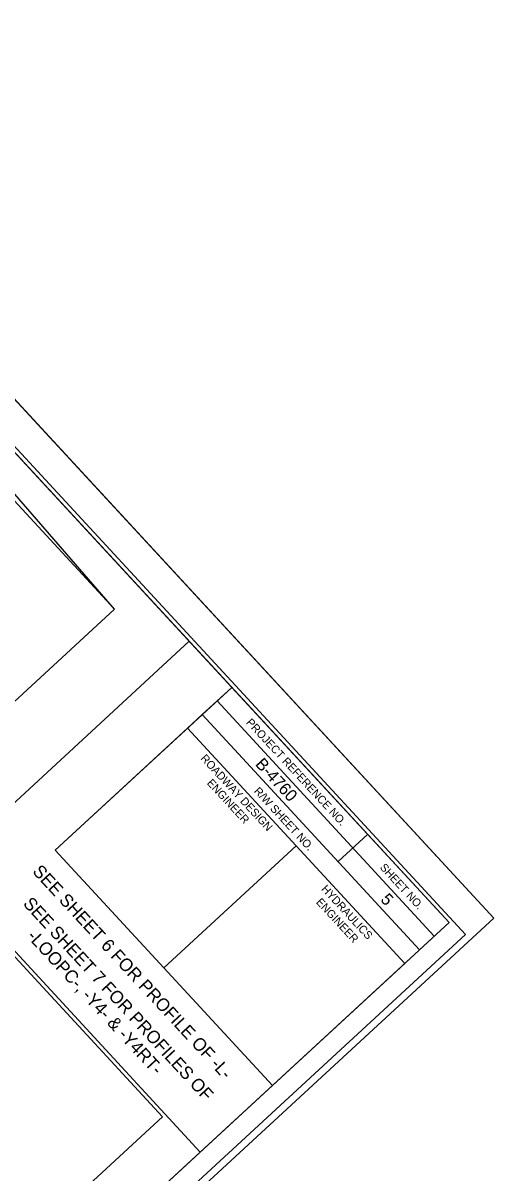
# Model space of a CAD drawing. Extents: x 1702837 to 1704783, y 793612 to 795591.
# Drawn here: x 1704489 to 1704783, y 794195 to 794914 of the extents above; entities that cross this region are included whole.
import ezdxf

# ---------------------------------------------------------------- set-up
doc = ezdxf.new("R2010")
doc.units = 0
for name, color, linetype in [('Old_Level_1', 7, 'Continuous'), ('Sheet Clip Boundary CELL', 7, 'Continuous'), ('Sheet Cutting Line CELL', 7, 'Continuous'), ('Sheet Data Field CELL', 7, 'Continuous'), ('Sheet Plan CELL', 7, 'Continuous'), ('Sheet Plan Layout CELL', 7, 'Continuous'), ('Sheet Plot Border Inside CELL', 7, 'Continuous'), ('Sheet Plot Border Outside CELL', 7, 'Continuous')]:
    doc.layers.add(name, color=color, linetype=linetype)

msp = doc.modelspace()

# ---------------------------------------------------------------- linework, layer by layer
at = {"layer": 'Sheet Clip Boundary CELL'}
for points in [[(1703013.13, 794728.35), (1703980.58, 793680.27), (1704576.46, 794230.31), (1704404.51, 794416.6), (1704546.5, 794547.66), (1703751.01, 795409.46)], [(1703542.14, 795216.65), (1703013.13, 794728.35), (1703980.58, 793680.27), (1704576.46, 794230.31), (1704404.51, 794416.6), (1704546.5, 794547.66), (1704231.02, 794911.54), (1704133.02, 794823), (1703864.61, 795110.34), (1703672.13, 795335.33)]]:
    msp.add_lwpolyline(points, close=True, dxfattribs=at)
at = {"layer": 'Sheet Cutting Line CELL'}
msp.add_line((1704783.42, 794354.44), (1703641.54, 795591.49), dxfattribs=at)
at = {"layer": 'Sheet Plan CELL'}
for p, q in [((1704610.46, 794490.18), (1704746.14, 794343.18)), ((1704601.25, 794481.67), (1704592.08, 794473.2)), ((1704601.25, 794481.67), (1704736.95, 794334.7)), ((1704601.25, 794481.67), (1704736.95, 794334.7)), ((1704704.42, 794406.78), (1704686.09, 794389.78)), ((1704659.94, 794399.68), (1704577.31, 794323.39))]:
    msp.add_line(p, q, dxfattribs=at)
for points in [[(1704755.38, 794351.66), (1703737.94, 795453.9), (1702966.4, 794741.71), (1703983.82, 793639.49)], [(1702966.4, 794741.71), (1703737.91, 795453.9), (1704619.69, 794498.69), (1704509.43, 794396.89), (1704645.1, 794249.9), (1703983.82, 793639.49)], [(1704619.69, 794498.69), (1704755.38, 794351.66), (1704736.95, 794334.7), (1704601.25, 794481.67)], [(1704592.08, 794473.2), (1704659.94, 794399.68), (1704577.26, 794323.37), (1704509.43, 794396.89)], [(1704659.94, 794399.68), (1704727.77, 794326.22), (1704645.1, 794249.9), (1704577.26, 794323.37)]]:
    msp.add_lwpolyline(points, close=True, dxfattribs=at)
at = {"layer": 'Sheet Plan Layout CELL'}
for points in [[(1703737.91, 795453.9), (1702966.4, 794741.71), (1703983.81, 793639.5), (1704599.96, 794208.24), (1704437.68, 794384.04), (1704593.08, 794527.49)], [(1704437.68, 794384.04), (1704599.97, 794208.22), (1704755.39, 794351.65), (1704593.08, 794527.49)]]:
    msp.add_lwpolyline(points, close=True, dxfattribs=at)
at = {"layer": 'Sheet Plot Border Inside CELL'}
msp.add_lwpolyline([(1702860.44, 794852.79), (1703990.45, 793628.62), (1704765.67, 794344.18), (1703635.66, 795568.37)], close=True, dxfattribs=at)
at = {"layer": 'Sheet Plot Border Outside CELL'}
msp.add_lwpolyline([(1702836.93, 794848.78), (1703978.81, 793611.73), (1704783.42, 794354.44), (1703641.54, 795591.49)], close=True, dxfattribs=at)

# ---------------------------------------------------------------- texts
at = {"layer": 'Old_Level_1'}
for s, p in [('SEE SHEET 6 FOR PROFILE OF -L-', (1704494.74, 794383.3)), ('SEE SHEET 7 FOR PROFILES OF ', (1704488.89, 794363.13)), ('-LOOPC-, -Y4- & -Y4RT-', (1704491.38, 794342.74))]:
    msp.add_text(s, height=8, rotation=312.70907, dxfattribs=at).set_placement(p)
at = {"layer": 'Sheet Data Field CELL'}
for s, p in [('B-4760', (1704633.9, 794450.37)), ('5', (1704712.12, 794365.73))]:
    msp.add_text(s, height=7.5, rotation=312.70907, dxfattribs=at).set_placement(p)
at = {"layer": 'Sheet Plan CELL'}
for s, height, p in [('PROJECT REFERENCE NO.', 5.0001, (1704628.33, 794476.46)), ('ROADWAY DESIGN', 5.0001, (1704599.85, 794454.01)), ('ENGINEER', 5, (1704603.8, 794438.62)), ('R/W SHEET NO.', 5.0001, (1704633.16, 794433.55)), ('SHEET NO.', 5, (1704711.79, 794385.88)), ('HYDRAULICS', 5, (1704675.25, 794372.36)), ('ENGINEER', 5, (1704671.95, 794364.2))]:
    msp.add_text(s, height=height, rotation=312.70907, dxfattribs=at).set_placement(p)

doc.saveas('drawing.dxf')
